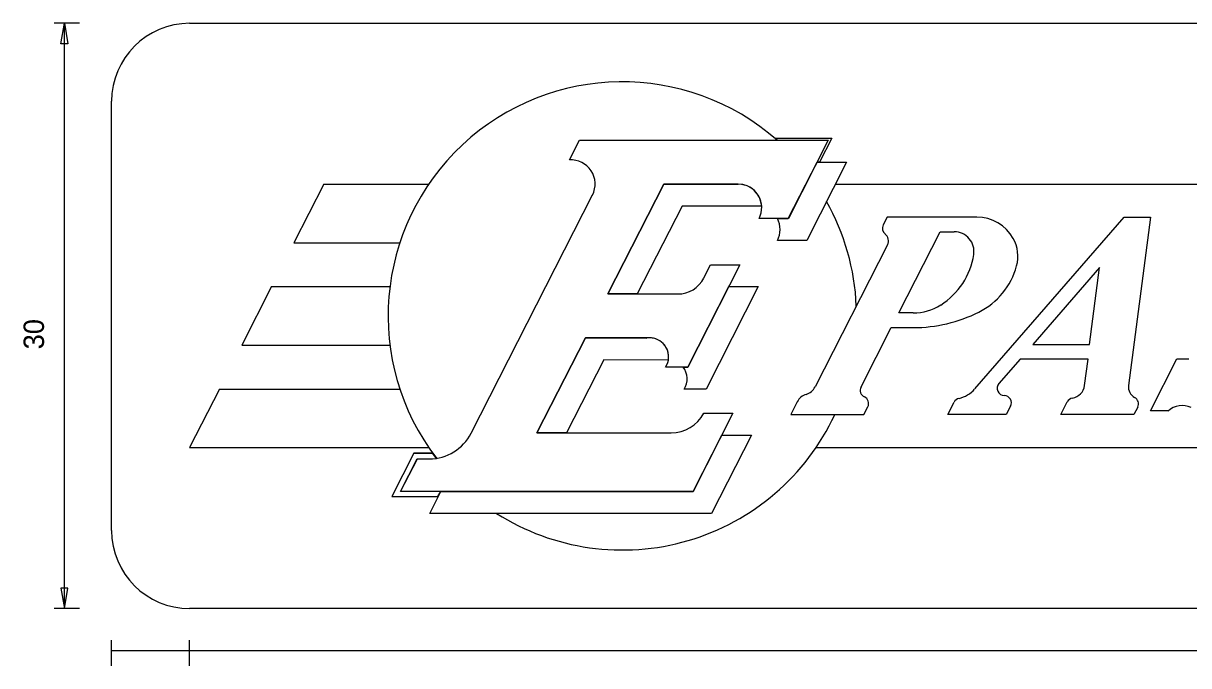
# Model space of a CAD drawing. Extents: x 10268197 to 10268826, y 2141503 to 2142677.
# Drawn here: x 10268598.38 to 10268633.6, y 2142371.58 to 2142391 of the extents above; entities that cross this region are included whole.
import ezdxf

# ---------------------------------------------------------------- set-up
doc = ezdxf.new("R2010")
doc.units = 0
doc.layers.add('GSBWFill', color=7, linetype='Continuous')
doc.layers.add('GSDims', color=7, linetype='Continuous')

msp = doc.modelspace()

# ---------------------------------------------------------------- linework, layer by layer
at = {"layer": 'GSBWFill'}
for p, q in [((10268603.406, 2142391.003), (10268648.239, 2142391.003)), ((10268601.047, 2142375.666), (10268601.047, 2142388.644)), ((10268621.091, 2142387.531), (10268622.815, 2142387.531)), ((10268622.815, 2142387.531), (10268622.443, 2142386.801)), ((10268614.884, 2142386.871), (10268615.186, 2142387.465)), ((10268615.186, 2142387.465), (10268622.707, 2142387.465)), ((10268622.707, 2142387.465), (10268621.503, 2142385.099)), ((10268621.501, 2142385.097), (10268622.37, 2142386.801)), ((10268621.501, 2142385.097), (10268622.37, 2142386.801)), ((10268623.264, 2142386.801), (10268622.058, 2142384.435)), ((10268623.264, 2142386.801), (10268622.058, 2142384.435)), ((10268622.37, 2142386.801), (10268623.264, 2142386.801)), ((10268622.37, 2142386.801), (10268623.264, 2142386.801)), ((10268607.46, 2142386.137), (10268606.559, 2142384.368)), ((10268607.46, 2142386.137), (10268610.632, 2142386.137)), ((10268617.735, 2142386.137), (10268616.045, 2142382.819)), ((10268616.045, 2142382.819), (10268617.735, 2142386.137)), ((10268616.045, 2142382.819), (10268617.735, 2142386.137)), ((10268619.99, 2142386.137), (10268617.735, 2142386.137)), ((10268617.735, 2142386.137), (10268619.99, 2142386.137)), ((10268617.735, 2142386.137), (10268619.99, 2142386.137)), ((10268622.925, 2142386.137), (10268648.163, 2142386.137)), ((10268611.912, 2142378.605), (10268615.583, 2142385.812)), ((10268618.291, 2142385.474), (10268616.938, 2142382.819)), ((10268618.291, 2142385.474), (10268616.938, 2142382.819)), ((10268620.698, 2142385.474), (10268618.291, 2142385.474)), ((10268620.698, 2142385.474), (10268618.291, 2142385.474)), ((10268621.503, 2142385.099), (10268620.617, 2142385.099)), ((10268621.172, 2142385.097), (10268621.501, 2142385.097)), ((10268621.172, 2142385.097), (10268621.501, 2142385.097)), ((10268624.493, 2142385.142), (10268624.373, 2142384.906)), ((10268627.202, 2142385.142), (10268624.493, 2142385.142)), ((10268627.135, 2142379.946), (10268631.653, 2142385.142)), ((10268631.653, 2142385.142), (10268632.449, 2142385.142)), ((10268632.449, 2142385.142), (10268631.787, 2142380.05)), ((10268606.559, 2142384.368), (10268609.761, 2142384.368)), ((10268622.058, 2142384.435), (10268621.173, 2142384.435)), ((10268622.058, 2142384.435), (10268621.173, 2142384.435)), ((10268624.84, 2142382.244), (10268626.092, 2142384.699)), ((10268626.092, 2142384.699), (10268626.518, 2142384.699)), ((10268624.501, 2142384.305), (10268622.31, 2142380.006)), ((10268620.039, 2142383.704), (10268618.462, 2142380.607)), ((10268618.95, 2142383.302), (10268619.154, 2142383.704)), ((10268619.154, 2142383.704), (10268620.039, 2142383.704)), ((10268630.912, 2142383.616), (10268628.892, 2142381.292)), ((10268630.609, 2142381.292), (10268630.912, 2142383.616)), ((10268605.884, 2142383.04), (10268604.983, 2142381.271)), ((10268605.884, 2142383.04), (10268609.461, 2142383.04)), ((10268618.462, 2142380.607), (10268619.701, 2142383.04)), ((10268618.462, 2142380.607), (10268619.701, 2142383.04)), ((10268620.595, 2142383.04), (10268619.017, 2142379.943)), ((10268620.595, 2142383.04), (10268619.017, 2142379.943)), ((10268619.701, 2142383.04), (10268620.595, 2142383.04)), ((10268619.701, 2142383.04), (10268620.595, 2142383.04)), ((10268616.045, 2142382.819), (10268618.161, 2142382.819)), ((10268616.938, 2142382.819), (10268616.045, 2142382.819)), ((10268616.938, 2142382.819), (10268616.045, 2142382.819)), ((10268625.279, 2142382.244), (10268624.84, 2142382.244)), ((10268623.7, 2142380.006), (10268624.615, 2142381.801)), ((10268624.615, 2142381.801), (10268625.279, 2142381.801)), ((10268604.983, 2142381.271), (10268609.461, 2142381.271)), ((10268615.369, 2142381.492), (10268613.903, 2142378.616)), ((10268613.903, 2142378.616), (10268615.369, 2142381.492)), ((10268613.903, 2142378.616), (10268615.369, 2142381.492)), ((10268617.31, 2142381.492), (10268615.369, 2142381.492)), ((10268615.369, 2142381.492), (10268617.227, 2142381.486)), ((10268615.369, 2142381.492), (10268617.227, 2142381.486)), ((10268628.892, 2142381.292), (10268630.609, 2142381.292)), ((10268628.509, 2142380.85), (10268627.867, 2142380.113)), ((10268630.564, 2142380.85), (10268628.509, 2142380.85)), ((10268630.459, 2142380.05), (10268630.564, 2142380.85)), ((10268632.446, 2142379.28), (10268633.249, 2142380.857)), ((10268633.249, 2142380.857), (10268633.604, 2142380.857)), ((10268615.923, 2142380.827), (10268614.797, 2142378.616)), ((10268615.923, 2142380.827), (10268614.797, 2142378.616)), ((10268617.877, 2142380.82), (10268615.923, 2142380.827)), ((10268617.877, 2142380.82), (10268615.923, 2142380.827)), ((10268618.462, 2142380.607), (10268617.795, 2142380.607)), ((10268618.322, 2142380.607), (10268618.462, 2142380.607)), ((10268618.322, 2142380.607), (10268618.462, 2142380.607)), ((10268604.307, 2142379.943), (10268603.406, 2142378.174)), ((10268604.307, 2142379.943), (10268609.761, 2142379.943)), ((10268619.017, 2142379.943), (10268618.353, 2142379.943)), ((10268619.017, 2142379.943), (10268618.353, 2142379.943)), ((10268621.772, 2142379.559), (10268621.574, 2142379.169)), ((10268626.321, 2142379.169), (10268626.513, 2142379.547)), ((10268628.221, 2142379.424), (10268628.09, 2142379.169)), ((10268629.735, 2142379.169), (10268629.931, 2142379.553)), ((10268619.83, 2142379.212), (10268618.625, 2142376.846)), ((10268618.945, 2142379.212), (10268619.83, 2142379.212)), ((10268621.574, 2142379.169), (10268623.786, 2142379.169)), ((10268623.786, 2142379.169), (10268623.906, 2142379.406)), ((10268628.09, 2142379.169), (10268626.321, 2142379.169)), ((10268631.947, 2142379.169), (10268629.735, 2142379.169)), ((10268632.063, 2142379.397), (10268631.947, 2142379.169)), ((10268632.984, 2142379.28), (10268632.446, 2142379.28)), ((10268613.903, 2142378.616), (10268617.964, 2142378.616)), ((10268614.797, 2142378.616), (10268613.903, 2142378.616)), ((10268614.797, 2142378.616), (10268613.903, 2142378.616)), ((10268618.625, 2142376.846), (10268619.492, 2142378.548)), ((10268618.625, 2142376.846), (10268619.492, 2142378.548)), ((10268620.386, 2142378.548), (10268619.18, 2142376.183)), ((10268620.386, 2142378.548), (10268619.18, 2142376.183)), ((10268619.492, 2142378.548), (10268620.386, 2142378.548)), ((10268619.492, 2142378.548), (10268620.386, 2142378.548)), ((10268603.406, 2142378.174), (10268610.632, 2142378.174)), ((10268622.338, 2142378.174), (10268644.105, 2142378.174)), ((10268610.186, 2142378.005), (10268609.52, 2142376.696)), ((10268609.777, 2142376.846), (10268610.279, 2142377.832)), ((10268610.186, 2142378.005), (10268610.751, 2142378.005)), ((10268610.279, 2142377.832), (10268610.65, 2142377.832)), ((10268609.52, 2142376.696), (10268610.908, 2142376.696)), ((10268618.625, 2142376.846), (10268609.777, 2142376.846)), ((10268610.661, 2142376.183), (10268610.999, 2142376.846)), ((10268610.661, 2142376.183), (10268610.999, 2142376.846)), ((10268610.999, 2142376.846), (10268618.625, 2142376.846)), ((10268610.999, 2142376.846), (10268618.625, 2142376.846)), ((10268619.18, 2142376.183), (10268610.661, 2142376.183)), ((10268619.18, 2142376.183), (10268610.661, 2142376.183)), ((10268648.239, 2142373.306), (10268603.406, 2142373.306))]:
    msp.add_line(p, q, dxfattribs=at)
for points in [[(10268621.091, 2142387.531), (10268622.815, 2142387.531), (10268622.443, 2142386.801), (10268622.37, 2142386.801), (10268622.707, 2142387.465), (10268621.167, 2142387.464)], [(10268610.751, 2142378.005), (10268610.186, 2142378.005), (10268609.52, 2142376.696), (10268610.908, 2142376.696), (10268610.999, 2142376.846), (10268609.777, 2142376.846), (10268610.292, 2142377.831), (10268610.655, 2142377.831), (10268610.867, 2142377.848)]]:
    msp.add_lwpolyline(points, close=True, dxfattribs=at)
for centre, radius, start, end in [((10268603.406, 2142388.644), 2.36, 90, 180), ((10268616.485, 2142382.155), 7.079, 48.5904, 217.4727), ((10268614.933, 2142386.142), 0.73, 332.9998, 93.8045), ((10268619.991, 2142385.429), 0.708, 332.2088, 90), ((10268619.991, 2142385.429), 0.708, 3.5833, 90), ((10268619.991, 2142385.429), 0.708, 3.5833, 90), ((10268616.485, 2142382.155), 7.079, 2.4236, 29.2771), ((10268620.546, 2142384.765), 0.708, 332.2088, 27.9127), ((10268620.546, 2142384.765), 0.708, 332.2088, 27.9127), ((10268627.202, 2142383.88), 1.261, 29.4315, 90), ((10268624.569, 2142384.805), 0.221, 152.9784, 231.1602), ((10268624.264, 2142384.425), 0.265, 333.0027, 51.1602), ((10268626.518, 2142384.101), 0.597, 351.076, 90), ((10268627.337, 2142383.956), 1.106, 344.7074, 29.4315), ((10268624.923, 2142384.352), 2.212, 302.4206, 351.076), ((10268626.27, 2142384.248), 2.212, 296.6431, 344.7074), ((10268618.161, 2142383.703), 0.885, 270, 332.9883), ((10268625.278, 2142383.792), 1.548, 270, 302.4206), ((10268625.278, 2142386.225), 4.424, 270, 296.6431), ((10268617.31, 2142380.916), 0.575, 350.3502, 98.3344), ((10268617.31, 2142380.916), 0.575, 350.3502, 98.3344), ((10268617.31, 2142380.916), 0.575, 327.421, 90), ((10268617.869, 2142380.252), 0.575, 327.421, 37.9799), ((10268617.869, 2142380.252), 0.575, 327.421, 37.9799), ((10268622.166, 2142379.358), 0.442, 106.4317, 152.9742), ((10268621.916, 2142380.206), 0.442, 286.4317, 332.9959), ((10268623.897, 2142379.905), 0.221, 152.9884, 244.7832), ((10268626.467, 2142380.525), 0.885, 282.7162, 318.9966), ((10268628.034, 2142379.967), 0.221, 138.9824, 268.6869), ((10268630.021, 2142380.107), 0.442, 279.2397, 352.5632), ((10268632.137, 2142380.004), 0.354, 172.5884, 241.8673), ((10268623.708, 2142379.505), 0.221, 333.0239, 64.7832), ((10268626.71, 2142379.446), 0.221, 102.7162, 153.0239), ((10268628.024, 2142379.525), 0.221, 332.9784, 88.6869), ((10268630.127, 2142379.452), 0.221, 99.2397, 153.0239), ((10268631.866, 2142379.497), 0.221, 332.9784, 61.8673), ((10268633.407, 2142378.827), 0.619, 64.3795, 133.1892), ((10268616.485, 2142382.155), 7.079, 237.5383, 335.047), ((10268617.963, 2142379.721), 1.106, 270, 332.5096), ((10268610.65, 2142379.247), 1.416, 270, 332.9991), ((10268603.406, 2142375.666), 2.36, 180, 270)]:
    msp.add_arc(centre, radius, start, end, dxfattribs=at)
at = {"layer": 'GSDims'}
for p, q in [((10268600.081, 2142391.003), (10268599.311, 2142391.003)), ((10268599.619, 2142373.306), (10268599.619, 2142391.003)), ((10268600.081, 2142373.306), (10268599.311, 2142373.306)), ((10268601.047, 2142371.577), (10268601.047, 2142372.347)), ((10268601.047, 2142372.039), (10268650.598, 2142372.039)), ((10268603.406, 2142371.577), (10268603.406, 2142372.347))]:
    msp.add_line(p, q, dxfattribs=at)
for points in [[(10268599.619, 2142391.003), (10268599.721, 2142390.387), (10268599.516, 2142390.387)], [(10268599.619, 2142373.306), (10268599.721, 2142373.922), (10268599.516, 2142373.922)]]:
    msp.add_lwpolyline(points, close=True, dxfattribs=at)

# ---------------------------------------------------------------- texts
msp.add_text('30', height=0.6159, rotation=90, dxfattribs=at).set_placement((10268599.003, 2142381.144))

doc.saveas('drawing.dxf')
